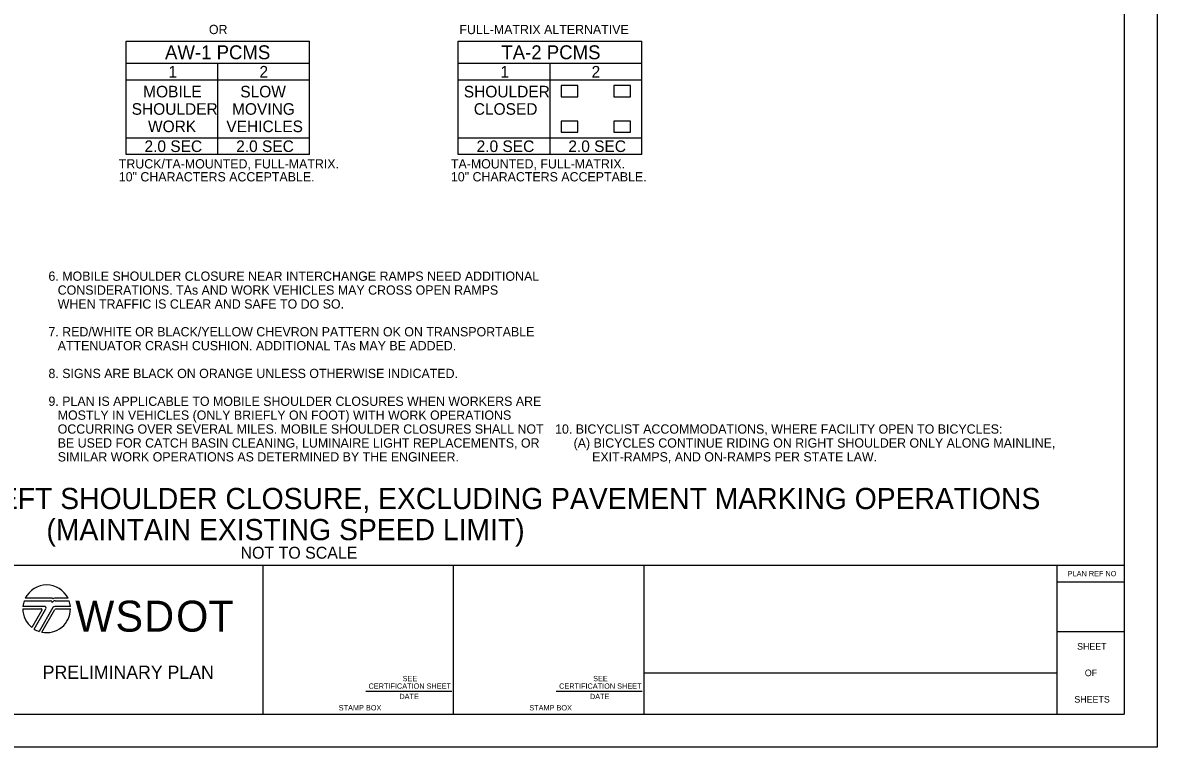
# Model space of a CAD drawing. Extents: x 0 to 17, y 0 to 11.
# Drawn here: x 8.43 to 17, y 0 to 5.47 of the extents above; entities that cross this region are included whole.
import ezdxf

# ---------------------------------------------------------------- set-up
doc = ezdxf.new("R2010")
doc.units = 0
for name, color, linetype in [('SH_GI_Logo_WSDOT', 7, 'Continuous'), ('SH_GI_PlotLimits', 7, 'Continuous'), ('SH_GI_SheetBorder1', 7, 'Continuous'), ('SH_GI_SheetBorder2', 7, 'Continuous'), ('SH_GI_SheetBorder3', 7, 'Continuous'), ('SH_GI_SheetTextInCells', 7, 'Continuous'), ('SH_GI_TitleBlockPrelimText', 7, 'Continuous'), ('TR_SN_ConstructionSigns', 7, 'Continuous'), ('TR_WZ_PortableChangeMessageSign', 7, 'Continuous'), ('TR_WZ_WorkZoneTextCurrent', 7, 'Continuous')]:
    doc.layers.add(name, color=color, linetype=linetype)

msp = doc.modelspace()

# ---------------------------------------------------------------- linework, layer by layer
at = {"layer": 'SH_GI_Logo_WSDOT'}
for p, q in [((8.6489, 1.1258), (8.4454, 1.1258)), ((8.7684, 1.1258), (8.6653, 1.1258)), ((8.4269, 1.0463), (8.5657, 1.0463)), ((8.59, 1.0643), (8.4278, 1.0643)), ((8.4377, 1.1078), (8.6354, 1.1078)), ((8.5709, 1.0373), (8.4948, 0.9054)), ((8.5121, 0.8933), (8.6004, 1.0463)), ((8.6541, 1.0553), (8.5502, 0.8754)), ((8.5713, 0.8698), (8.6697, 1.0403)), ((8.786, 1.0643), (8.6697, 1.0643)), ((8.6705, 1.1078), (8.776, 1.1078)), ((8.6801, 1.0463), (8.7869, 1.0463))]:
    msp.add_line(p, q, dxfattribs=at)
for centre, radius, start, end in [((8.6069, 1.0463), 0.18, 26.21027, 153.78973), ((8.6489, 1.1198), 0.006, 0, 90), ((8.6653, 1.1138), 0.012, 90, 150), ((8.6069, 1.0463), 0.18, 180, 231.49627), ((8.6069, 1.0463), 0.18, 160.02155, 174.26083), ((8.5657, 1.0403), 0.006, 330, 90), ((8.6069, 1.0463), 0.18, 258.58993, 0), ((8.59, 1.0523), 0.012, 330, 90), ((8.6354, 1.0943), 0.0135, 360, 90), ((8.6705, 1.0838), 0.024, 90.00001, 154.05552), ((8.6697, 1.0463), 0.018, 90, 150), ((8.6801, 1.0343), 0.012, 90, 150), ((8.6069, 1.0463), 0.18, 5.73917, 19.97845), ((8.6069, 1.0463), 0.18, 238.21167, 251.66132)]:
    msp.add_arc(centre, radius, start, end, dxfattribs=at)
at = {"layer": 'SH_GI_PlotLimits'}
msp.add_lwpolyline([(0, 11), (17, 11), (17, 0), (0, 0)], close=True, dxfattribs=at)
at = {"layer": 'SH_GI_SheetBorder1'}
for p, q in [((11.0184, 0.4233), (11.6683, 0.4233)), ((12.4584, 0.4233), (13.1083, 0.4233))]:
    msp.add_line(p, q, dxfattribs=at)
at = {"layer": 'SH_GI_SheetBorder2'}
msp.add_line((13.12, 0.5625), (16.24, 0.5625), dxfattribs=at)
at = {"layer": 'SH_GI_SheetBorder3'}
for p, q in [((16.75, 10.75), (16.75, 0.25)), ((1, 1.375), (16.75, 1.375)), ((10.24, 1.375), (10.24, 0.25)), ((11.68, 1.3759), (11.68, 0.25)), ((13.12, 1.3759), (13.12, 0.25)), ((16.24, 1.375), (16.24, 0.25)), ((16.24, 1.25), (16.75, 1.25)), ((16.24, 0.875), (16.75, 0.875)), ((1, 0.25), (16.75, 0.25))]:
    msp.add_line(p, q, dxfattribs=at)
at = {"layer": 'TR_WZ_PortableChangeMessageSign'}
for p, q in [((9.2079, 5.3353), (10.5939, 5.3353)), ((9.2079, 4.4785), (9.2079, 5.3353)), ((10.5939, 4.4785), (10.5939, 5.3353)), ((11.7178, 5.3353), (13.1038, 5.3353)), ((11.7178, 4.4785), (11.7178, 5.3353)), ((13.1038, 4.4785), (13.1038, 5.3353)), ((10.5939, 5.1673), (9.2079, 5.1673)), ((9.9009, 4.4785), (9.9009, 5.1673)), ((13.1038, 5.1673), (11.7178, 5.1673)), ((12.4108, 4.4785), (12.4108, 5.1673)), ((9.9009, 5.0413), (9.2079, 5.0413)), ((10.5939, 5.0413), (9.9009, 5.0413)), ((12.4108, 5.0413), (11.7178, 5.0413)), ((13.1038, 5.0413), (12.4108, 5.0413)), ((9.2079, 4.6045), (9.9009, 4.6045)), ((9.9009, 4.6045), (10.5939, 4.6045)), ((11.7178, 4.6045), (12.4108, 4.6045)), ((12.4108, 4.6045), (13.1038, 4.6045)), ((10.5939, 4.4785), (9.2079, 4.4785)), ((13.1038, 4.4785), (11.7178, 4.4785))]:
    msp.add_line(p, q, dxfattribs=at)
for points in [[(12.6208, 4.9993), (12.4948, 4.9993), (12.4948, 4.9153), (12.6208, 4.9153)], [(13.0198, 4.9993), (12.8938, 4.9993), (12.8938, 4.9153), (13.0198, 4.9153)], [(12.6208, 4.7305), (12.4948, 4.7305), (12.4948, 4.6465), (12.6208, 4.6465)], [(13.0198, 4.7305), (12.8938, 4.7305), (12.8938, 4.6465), (13.0198, 4.6465)]]:
    msp.add_lwpolyline(points, close=True, dxfattribs=at)

# ---------------------------------------------------------------- texts
at = {"layer": 'SH_GI_Logo_WSDOT'}
for s, p in [('W', (8.8225, 0.8739)), ('S', (9.1268, 0.8739)), ('D', (9.3442, 0.8739)), ('O', (9.5854, 0.8739)), ('T', (9.8296, 0.8739))]:
    msp.add_text(s, height=0.234, dxfattribs=at).set_placement(p)
at = {"layer": 'SH_GI_SheetTextInCells'}
for s, height, p in [('PLAN REF NO', 0.04, (16.3228, 1.2925)), ('SHEET', 0.05, (16.394, 0.7375)), ('SEE', 0.04, (11.2966, 0.4995)), ('SEE', 0.04, (12.7366, 0.4995)), ('OF', 0.05, (16.4521, 0.5375)), ('CERTIFICATION SHEET', 0.04, (11.0393, 0.4425)), ('CERTIFICATION SHEET', 0.04, (12.4793, 0.4425)), ('DATE', 0.04, (11.2723, 0.3641)), ('DATE', 0.04, (12.7123, 0.3641)), ('SHEETS', 0.05, (16.3733, 0.3375)), ('STAMP BOX', 0.04, (10.8141, 0.2786)), ('STAMP BOX', 0.04, (12.2541, 0.2786))]:
    msp.add_text(s, height=height, dxfattribs=at).set_placement(p)
at = {"layer": 'SH_GI_TitleBlockPrelimText'}
msp.add_text('PRELIMINARY PLAN', height=0.1, dxfattribs=at).set_placement((8.5768, 0.5173))
at = {"layer": 'TR_SN_ConstructionSigns'}
for s, p in [('OR', (9.833, 5.3886)), ('FULL-MATRIX ALTERNATIVE', (11.7261, 5.3886))]:
    msp.add_text(s, height=0.07, dxfattribs=at).set_placement(p)
at = {"layer": 'TR_WZ_PortableChangeMessageSign'}
for s, height, p in [('AW-1 PCMS', 0.105, (9.5011, 5.1988)), ('TA-2 PCMS', 0.105, (12.0431, 5.1988)), ('1', 0.0875, (9.527, 5.0605)), ('2', 0.0875, (10.215, 5.0605)), ('1', 0.0875, (12.0369, 5.0605)), ('2', 0.0875, (12.7249, 5.0605)), ('MOBILE', 0.0875, (9.3362, 4.9104)), ('SLOW', 0.0875, (10.0701, 4.9104)), ('SHOULDER', 0.0875, (11.7592, 4.9104)), ('SHOULDER', 0.0875, (9.2494, 4.7791)), ('MOVING', 0.0875, (10.0077, 4.7791)), ('CLOSED', 0.0875, (11.8346, 4.7791)), ('WORK', 0.0875, (9.3727, 4.6479)), ('VEHICLES', 0.0875, (9.9648, 4.6479)), ('2.0 SEC', 0.0875, (9.3462, 4.4977)), ('2.0 SEC', 0.0875, (10.0392, 4.4977)), ('2.0 SEC', 0.0875, (11.8561, 4.4977)), ('2.0 SEC', 0.0875, (12.5491, 4.4977)), ('TRUCK/TA-MOUNTED, FULL-MATRIX.', 0.07, (9.152, 4.3735)), ('TA-MOUNTED, FULL-MATRIX.', 0.07, (11.6618, 4.3735)), ('10" CHARACTERS ACCEPTABLE.', 0.07, (9.152, 4.2755)), ('10" CHARACTERS ACCEPTABLE.', 0.07, (11.6618, 4.2755))]:
    msp.add_text(s, height=height, rotation=360, dxfattribs=at).set_placement(p)
at = {"layer": 'TR_WZ_WorkZoneTextCurrent'}
for s, height, p in [('6. MOBILE SHOULDER CLOSURE NEAR INTERCHANGE RAMPS NEED ADDITIONAL ', 0.07, (8.6204, 3.5247)), ('CONSIDERATIONS. TAs AND WORK VEHICLES MAY CROSS OPEN RAMPS ', 0.07, (8.6904, 3.4197)), ('WHEN TRAFFIC IS CLEAR AND SAFE TO DO SO.', 0.07, (8.6904, 3.3147)), ('7. RED/WHITE OR BLACK/YELLOW CHEVRON PATTERN OK ON TRANSPORTABLE ', 0.07, (8.6204, 3.1047)), ('ATTENUATOR CRASH CUSHION. ADDITIONAL TAs MAY BE ADDED.', 0.07, (8.6904, 2.9997)), ('8. SIGNS ARE BLACK ON ORANGE UNLESS OTHERWISE INDICATED.', 0.07, (8.6204, 2.7897)), ('9. PLAN IS APPLICABLE TO MOBILE SHOULDER CLOSURES WHEN WORKERS ARE ', 0.07, (8.6204, 2.5797)), ('MOSTLY IN VEHICLES (ONLY BRIEFLY ON FOOT) WITH WORK OPERATIONS ', 0.07, (8.6904, 2.4747)), ('OCCURRING OVER SEVERAL MILES. MOBILE SHOULDER CLOSURES SHALL NOT ', 0.07, (8.6904, 2.3697)), ('10. BICYCLIST ACCOMMODATIONS, WHERE FACILITY OPEN TO BICYCLES:', 0.07, (12.449, 2.3697)), ('BE USED FOR CATCH BASIN CLEANING, LUMINAIRE LIGHT REPLACEMENTS, OR ', 0.07, (8.6904, 2.2647)), ('(A) BICYCLES CONTINUE RIDING ON RIGHT SHOULDER ONLY ALONG MAINLINE,   ', 0.07, (12.589, 2.2647)), ('SIMILAR WORK OPERATIONS AS DETERMINED BY THE ENGINEER.', 0.07, (8.6904, 2.1597)), ('EXIT-RAMPS, AND ON-RAMPS PER STATE LAW.', 0.07, (12.729, 2.1597)), ('FREEWAY (2+ LANES): MOBILE LEFT SHOULDER CLOSURE, EXCLUDING PAVEMENT MARKING OPERATIONS', 0.16, (4.8752, 1.7997)), ('(MAINTAIN EXISTING SPEED LIMIT)', 0.16, (8.6051, 1.565)), ('NOT TO SCALE', 0.09, (10.0722, 1.425))]:
    msp.add_text(s, height=height, rotation=360, dxfattribs=at).set_placement(p)

doc.saveas('drawing.dxf')
